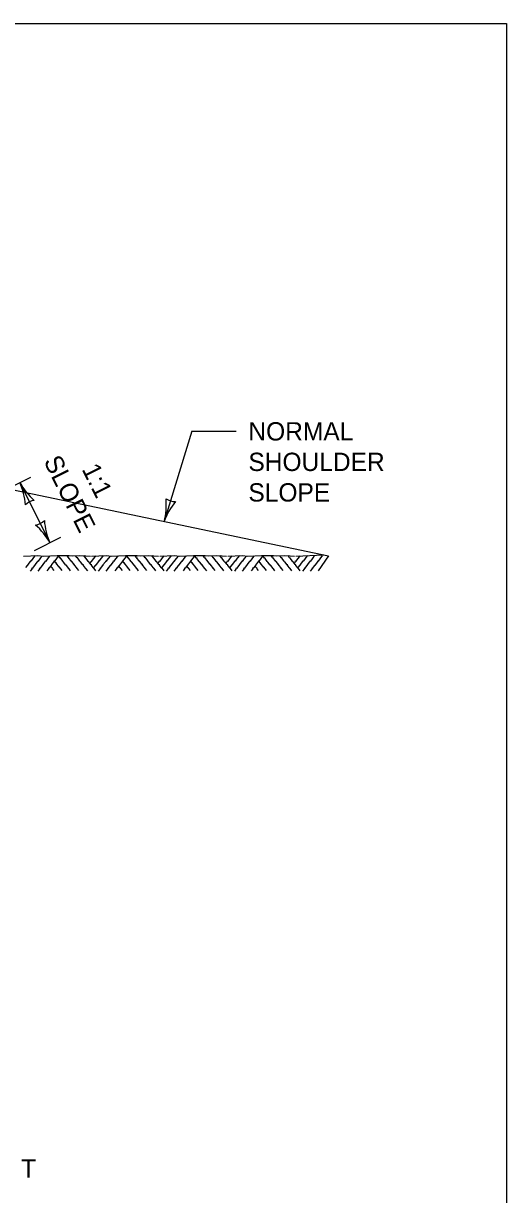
# Model space of a CAD drawing. Extents: x 49991.4 to 50022.1, y 49985 to 50011.4.
# Drawn here: x 50015.17 to 50016.75, y 49995.163 to 49998.999 of the extents above; entities that cross this region are included whole.
import ezdxf

# ---------------------------------------------------------------- set-up
doc = ezdxf.new("R2010")
doc.units = 0
for name, color, linetype in [('Level 1', 7, 'Continuous'), ('Level 2', 7, 'Continuous'), ('Level 3', 7, 'Continuous'), ('Level 4', 7, 'Continuous')]:
    doc.layers.add(name, color=color, linetype=linetype)

msp = doc.modelspace()

# ---------------------------------------------------------------- linework, layer by layer
at = {"layer": 'Level 1'}
msp.add_line((50016.1675, 49997.2547), (50016.1336, 49997.2064), dxfattribs=at)
msp.add_lwpolyline([(49999.3835, 49998.9992), (50016.7501, 49998.9992), (50016.7501, 49987.7988), (49999.3835, 49987.7988)], close=True, dxfattribs=at)
for points in [[(50015.1698, 49997.2545), (50015.217, 49997.2564), (50015.2349, 49997.2545), (50015.2805, 49997.256), (50015.3189, 49997.2562), (50015.3296, 49997.2548), (50015.3546, 49997.2564), (50015.3738, 49997.2554), (50015.3885, 49997.2545)], [(50015.2078, 49997.2562), (50015.2018, 49997.249), (50015.2025, 49997.2474), (50015.201, 49997.2474), (50015.1936, 49997.238), (50015.1916, 49997.238), (50015.192, 49997.2364), (50015.1842, 49997.2268), (50015.1842, 49997.2248), (50015.1826, 49997.2244), (50015.1764, 49997.2164)], [(50015.2302, 49997.2544), (50015.2247, 49997.2478), (50015.2256, 49997.2462), (50015.2241, 49997.2462), (50015.2166, 49997.2368), (50015.2146, 49997.2368), (50015.2148, 49997.235), (50015.2072, 49997.2254), (50015.2072, 49997.2234), (50015.2056, 49997.223), (50015.1982, 49997.2134), (50015.1965, 49997.2134), (50015.1968, 49997.2114), (50015.1916, 49997.2052)], [(50015.2559, 49997.2552), (50015.2499, 49997.2479), (50015.2506, 49997.2464), (50015.2492, 49997.2464), (50015.2418, 49997.237), (50015.2397, 49997.237), (50015.24, 49997.2352), (50015.2325, 49997.2256), (50015.2325, 49997.2239), (50015.2307, 49997.2232), (50015.2235, 49997.2138), (50015.2216, 49997.2136), (50015.222, 49997.2119), (50015.2168, 49997.2053)], [(50015.2853, 49997.256), (50015.2793, 49997.2488), (50015.28, 49997.2473), (50015.2787, 49997.2473), (50015.2712, 49997.238), (50015.2694, 49997.238), (50015.2696, 49997.236), (50015.2619, 49997.2264), (50015.2619, 49997.2248), (50015.2602, 49997.224), (50015.2529, 49997.2148), (50015.2512, 49997.2144), (50015.2514, 49997.2128), (50015.2463, 49997.2064)], [(50015.3237, 49997.2064), (50015.3189, 49997.2126), (50015.3174, 49997.2124), (50015.3177, 49997.2138), (50015.3102, 49997.223), (50015.3106, 49997.225), (50015.3087, 49997.225), (50015.3012, 49997.2348), (50015.2994, 49997.2352), (50015.2992, 49997.2368), (50015.2918, 49997.2462), (50015.2919, 49997.2479), (50015.2901, 49997.248), (50015.285, 49997.2546)], [(50015.3512, 49997.2068), (50015.3456, 49997.2142), (50015.3438, 49997.2138), (50015.3442, 49997.2154), (50015.3368, 49997.2246), (50015.337, 49997.2264), (50015.3354, 49997.2268), (50015.3278, 49997.2364), (50015.3261, 49997.2366), (50015.3258, 49997.2384), (50015.3182, 49997.2478), (50015.3186, 49997.2496), (50015.3166, 49997.2496), (50015.3116, 49997.2562)], [(50015.3798, 49997.2064), (50015.3742, 49997.2134), (50015.3728, 49997.2132), (50015.373, 49997.2144), (50015.3656, 49997.2239), (50015.366, 49997.2258), (50015.364, 49997.226), (50015.3566, 49997.2354), (50015.3548, 49997.2359), (50015.3546, 49997.2378), (50015.3471, 49997.247), (50015.3472, 49997.2488), (50015.3456, 49997.2488), (50015.3405, 49997.2554)], [(50015.3903, 49997.2268), (50015.3832, 49997.2358), (50015.3816, 49997.236), (50015.3813, 49997.2378), (50015.3736, 49997.2472), (50015.3741, 49997.249), (50015.3722, 49997.249), (50015.3669, 49997.2558)], [(50015.4059, 49997.255), (50015.3999, 49997.2479), (50015.4006, 49997.2464), (50015.3992, 49997.2464), (50015.3916, 49997.237), (50015.3908, 49997.237)], [(50015.3926, 49997.2545), (50015.4398, 49997.2564), (50015.4576, 49997.2545), (50015.5032, 49997.256), (50015.5416, 49997.2562), (50015.5523, 49997.2548), (50015.5772, 49997.2564), (50015.5964, 49997.2554), (50015.6112, 49997.2545)], [(50015.4305, 49997.2562), (50015.4245, 49997.249), (50015.4252, 49997.2474), (50015.4238, 49997.2474), (50015.4164, 49997.238), (50015.4143, 49997.238), (50015.4148, 49997.2364), (50015.4071, 49997.2268), (50015.4071, 49997.2248), (50015.4053, 49997.2244), (50015.3993, 49997.2164)], [(50015.453, 49997.2544), (50015.4476, 49997.2478), (50015.448, 49997.2462), (50015.4467, 49997.2462), (50015.4392, 49997.2368), (50015.4374, 49997.2368), (50015.4376, 49997.235), (50015.4299, 49997.2254), (50015.4299, 49997.2234), (50015.4284, 49997.223), (50015.421, 49997.2134), (50015.4192, 49997.2134), (50015.4196, 49997.2114), (50015.4143, 49997.2052)], [(50015.4786, 49997.2552), (50015.4726, 49997.2479), (50015.4734, 49997.2464), (50015.4719, 49997.2464), (50015.4644, 49997.237), (50015.4626, 49997.237), (50015.4629, 49997.2352), (50015.4551, 49997.2256), (50015.4551, 49997.2239), (50015.4536, 49997.2232), (50015.4462, 49997.2138), (50015.4443, 49997.2136), (50015.4448, 49997.2119), (50015.4395, 49997.2053)], [(50015.508, 49997.256), (50015.502, 49997.2488), (50015.5028, 49997.2473), (50015.5016, 49997.2473), (50015.4941, 49997.238), (50015.4922, 49997.238), (50015.4923, 49997.236), (50015.4846, 49997.2264), (50015.4846, 49997.2248), (50015.483, 49997.224), (50015.4756, 49997.2148), (50015.474, 49997.2144), (50015.4743, 49997.2128), (50015.469, 49997.2064)], [(50015.5466, 49997.2064), (50015.5418, 49997.2126), (50015.5402, 49997.2124), (50015.5406, 49997.2138), (50015.5331, 49997.223), (50015.5334, 49997.225), (50015.5316, 49997.225), (50015.5241, 49997.2348), (50015.5223, 49997.2352), (50015.522, 49997.2368), (50015.5145, 49997.2462), (50015.5148, 49997.2479), (50015.513, 49997.248), (50015.5079, 49997.2546)], [(50015.5738, 49997.2068), (50015.5682, 49997.2142), (50015.5666, 49997.2138), (50015.567, 49997.2154), (50015.5595, 49997.2246), (50015.5598, 49997.2264), (50015.5582, 49997.2268), (50015.5505, 49997.2364), (50015.5487, 49997.2366), (50015.5486, 49997.2384), (50015.5409, 49997.2478), (50015.5412, 49997.2496), (50015.5394, 49997.2496), (50015.5343, 49997.2562)], [(50015.6026, 49997.2064), (50015.597, 49997.2134), (50015.5955, 49997.2132), (50015.5958, 49997.2144), (50015.5883, 49997.2239), (50015.5888, 49997.2258), (50015.5868, 49997.226), (50015.5793, 49997.2354), (50015.5775, 49997.2359), (50015.5772, 49997.2378), (50015.5697, 49997.247), (50015.5702, 49997.2488), (50015.5682, 49997.2488), (50015.5632, 49997.2554)], [(50015.613, 49997.2268), (50015.606, 49997.2358), (50015.6042, 49997.236), (50015.604, 49997.2378), (50015.5964, 49997.2472), (50015.5967, 49997.249), (50015.5949, 49997.249), (50015.5895, 49997.2558)], [(50015.6286, 49997.255), (50015.6226, 49997.2479), (50015.6234, 49997.2464), (50015.6219, 49997.2464), (50015.6144, 49997.237), (50015.6135, 49997.237)], [(50015.6156, 49997.2545), (50015.6626, 49997.2564), (50015.6804, 49997.2545), (50015.726, 49997.256), (50015.7644, 49997.2562), (50015.775, 49997.2548), (50015.8001, 49997.2564), (50015.8193, 49997.2554), (50015.834, 49997.2545)], [(50015.6532, 49997.2562), (50015.6472, 49997.249), (50015.648, 49997.2474), (50015.6465, 49997.2474), (50015.6392, 49997.238), (50015.637, 49997.238), (50015.6375, 49997.2364), (50015.6297, 49997.2268), (50015.6297, 49997.2248), (50015.628, 49997.2244), (50015.622, 49997.2164)], [(50015.6758, 49997.2544), (50015.6702, 49997.2478), (50015.6708, 49997.2462), (50015.6696, 49997.2462), (50015.6621, 49997.2368), (50015.6602, 49997.2368), (50015.6603, 49997.235), (50015.6526, 49997.2254), (50015.6526, 49997.2234), (50015.6512, 49997.223), (50015.6438, 49997.2134), (50015.642, 49997.2134), (50015.6423, 49997.2114), (50015.637, 49997.2052)], [(50015.7014, 49997.2552), (50015.6954, 49997.2479), (50015.6962, 49997.2464), (50015.6946, 49997.2464), (50015.6873, 49997.237), (50015.6852, 49997.237), (50015.6856, 49997.2352), (50015.678, 49997.2256), (50015.678, 49997.2239), (50015.6762, 49997.2232), (50015.669, 49997.2138), (50015.667, 49997.2136), (50015.6675, 49997.2119), (50015.6622, 49997.2053)], [(50015.7308, 49997.256), (50015.7248, 49997.2488), (50015.7256, 49997.2473), (50015.7242, 49997.2473), (50015.7167, 49997.238), (50015.7149, 49997.238), (50015.715, 49997.236), (50015.7074, 49997.2264), (50015.7074, 49997.2248), (50015.7058, 49997.224), (50015.6984, 49997.2148), (50015.6968, 49997.2144), (50015.697, 49997.2128), (50015.6918, 49997.2064)], [(50015.7692, 49997.2064), (50015.7644, 49997.2126), (50015.7629, 49997.2124), (50015.7632, 49997.2138), (50015.7556, 49997.223), (50015.7562, 49997.225), (50015.7542, 49997.225), (50015.7467, 49997.2348), (50015.745, 49997.2352), (50015.7448, 49997.2368), (50015.7372, 49997.2462), (50015.7376, 49997.2479), (50015.7358, 49997.248), (50015.7306, 49997.2546)], [(50015.7966, 49997.2068), (50015.7911, 49997.2142), (50015.7893, 49997.2138), (50015.7898, 49997.2154), (50015.7822, 49997.2246), (50015.7826, 49997.2264), (50015.7809, 49997.2268), (50015.7732, 49997.2364), (50015.7716, 49997.2366), (50015.7713, 49997.2384), (50015.7638, 49997.2478), (50015.7641, 49997.2496), (50015.7622, 49997.2496), (50015.757, 49997.2562)], [(50015.8253, 49997.2064), (50015.8198, 49997.2134), (50015.8182, 49997.2132), (50015.8186, 49997.2144), (50015.811, 49997.2239), (50015.8115, 49997.2258), (50015.8096, 49997.226), (50015.802, 49997.2354), (50015.8004, 49997.2359), (50015.8001, 49997.2378), (50015.7926, 49997.247), (50015.7929, 49997.2488), (50015.7911, 49997.2488), (50015.786, 49997.2554)], [(50015.8358, 49997.2268), (50015.8288, 49997.2358), (50015.8271, 49997.236), (50015.8268, 49997.2378), (50015.8192, 49997.2472), (50015.8196, 49997.249), (50015.8176, 49997.249), (50015.8122, 49997.2558)], [(50015.8514, 49997.255), (50015.8454, 49997.2479), (50015.8462, 49997.2464), (50015.8446, 49997.2464), (50015.8372, 49997.237), (50015.8362, 49997.237)], [(50015.838, 49997.2545), (50015.8853, 49997.2564), (50015.9032, 49997.2545), (50015.9488, 49997.256), (50015.9872, 49997.2562), (50015.9978, 49997.2548), (50016.0227, 49997.2564), (50016.042, 49997.2554), (50016.0568, 49997.2545)], [(50015.876, 49997.2562), (50015.87, 49997.249), (50015.8708, 49997.2474), (50015.8692, 49997.2474), (50015.8619, 49997.238), (50015.8598, 49997.238), (50015.8602, 49997.2364), (50015.8526, 49997.2268), (50015.8526, 49997.2248), (50015.8508, 49997.2244), (50015.8448, 49997.2164)], [(50015.8985, 49997.2544), (50015.8931, 49997.2478), (50015.8937, 49997.2462), (50015.8922, 49997.2462), (50015.8847, 49997.2368), (50015.8829, 49997.2368), (50015.883, 49997.235), (50015.8754, 49997.2254), (50015.8754, 49997.2234), (50015.8739, 49997.223), (50015.8664, 49997.2134), (50015.8648, 49997.2134), (50015.865, 49997.2114), (50015.8598, 49997.2052)], [(50015.9242, 49997.2552), (50015.9182, 49997.2479), (50015.9189, 49997.2464), (50015.9174, 49997.2464), (50015.91, 49997.237), (50015.9081, 49997.237), (50015.9084, 49997.2352), (50015.9008, 49997.2256), (50015.9008, 49997.2239), (50015.8991, 49997.2232), (50015.8918, 49997.2138), (50015.8898, 49997.2136), (50015.8902, 49997.2119), (50015.885, 49997.2053)], [(50015.9536, 49997.256), (50015.9477, 49997.2488), (50015.9483, 49997.2473), (50015.9471, 49997.2473), (50015.9396, 49997.238), (50015.9376, 49997.238), (50015.9378, 49997.236), (50015.9302, 49997.2264), (50015.9302, 49997.2248), (50015.9285, 49997.224), (50015.9212, 49997.2148), (50015.9195, 49997.2144), (50015.9198, 49997.2128), (50015.9146, 49997.2064)], [(50015.9921, 49997.2064), (50015.9872, 49997.2126), (50015.9856, 49997.2124), (50015.9861, 49997.2138), (50015.9786, 49997.223), (50015.9789, 49997.225), (50015.9771, 49997.225), (50015.9696, 49997.2348), (50015.9676, 49997.2352), (50015.9675, 49997.2368), (50015.96, 49997.2462), (50015.9602, 49997.2479), (50015.9585, 49997.248), (50015.9534, 49997.2546)], [(50016.0194, 49997.2068), (50016.0137, 49997.2142), (50016.012, 49997.2138), (50016.0125, 49997.2154), (50016.005, 49997.2246), (50016.0053, 49997.2264), (50016.0036, 49997.2268), (50015.996, 49997.2364), (50015.9942, 49997.2366), (50015.994, 49997.2384), (50015.9864, 49997.2478), (50015.9867, 49997.2496), (50015.9849, 49997.2496), (50015.9798, 49997.2562)], [(50016.048, 49997.2064), (50016.0425, 49997.2134), (50016.041, 49997.2132), (50016.0413, 49997.2144), (50016.0338, 49997.2239), (50016.0342, 49997.2258), (50016.0326, 49997.226), (50016.0248, 49997.2354), (50016.0232, 49997.2359), (50016.0227, 49997.2378), (50016.0152, 49997.247), (50016.0156, 49997.2488), (50016.0137, 49997.2488), (50016.0088, 49997.2554)], [(50016.0586, 49997.2268), (50016.0515, 49997.2358), (50016.0497, 49997.236), (50016.0496, 49997.2378), (50016.0419, 49997.2472), (50016.0422, 49997.249), (50016.0404, 49997.249), (50016.0352, 49997.2558)], [(50016.0742, 49997.255), (50016.0682, 49997.2479), (50016.0689, 49997.2464), (50016.0674, 49997.2464), (50016.0599, 49997.237), (50016.059, 49997.237)], [(50016.0608, 49997.2545), (50016.1512, 49997.2581)], [(50016.0988, 49997.2562), (50016.0928, 49997.249), (50016.0935, 49997.2474), (50016.092, 49997.2474), (50016.0846, 49997.238), (50016.0826, 49997.238), (50016.083, 49997.2364), (50016.0752, 49997.2268), (50016.0752, 49997.2248), (50016.0736, 49997.2244), (50016.0676, 49997.2164)], [(50016.1212, 49997.2544), (50016.1157, 49997.2478), (50016.1166, 49997.2462), (50016.1151, 49997.2462), (50016.1076, 49997.2368), (50016.1056, 49997.2368), (50016.1058, 49997.235), (50016.0982, 49997.2254), (50016.0982, 49997.2234), (50016.0966, 49997.223), (50016.0893, 49997.2134), (50016.0875, 49997.2134), (50016.0878, 49997.2114), (50016.0826, 49997.2052)], [(50016.1469, 49997.2552), (50016.1409, 49997.2479), (50016.1416, 49997.2464), (50016.1402, 49997.2464), (50016.1326, 49997.237), (50016.1307, 49997.237), (50016.1312, 49997.2352), (50016.1235, 49997.2256), (50016.1235, 49997.2239), (50016.1217, 49997.2232), (50016.1145, 49997.2138), (50016.1126, 49997.2136), (50016.113, 49997.2119), (50016.1078, 49997.2053)], [(50015.2706, 49997.2066), (50015.2652, 49997.2134), (50015.2655, 49997.215), (50015.2636, 49997.2154), (50015.2586, 49997.2218)], [(50015.2962, 49997.2072), (50015.2876, 49997.218), (50015.2859, 49997.2185), (50015.2858, 49997.2203), (50015.2782, 49997.2294), (50015.2784, 49997.2314), (50015.2766, 49997.2314), (50015.2716, 49997.2378)], [(50015.3906, 49997.237), (50015.3896, 49997.237), (50015.3897, 49997.2352), (50015.387, 49997.2316)], [(50015.4068, 49997.2065), (50015.4014, 49997.2136), (50015.3998, 49997.2132), (50015.4, 49997.2148), (50015.3926, 49997.224), (50015.393, 49997.226), (50015.3912, 49997.2262), (50015.3908, 49997.2268)], [(50015.4932, 49997.2066), (50015.4881, 49997.2134), (50015.4882, 49997.215), (50015.4863, 49997.2154), (50015.4812, 49997.2218)], [(50015.519, 49997.2072), (50015.5103, 49997.218), (50015.5086, 49997.2185), (50015.5085, 49997.2203), (50015.501, 49997.2294), (50015.5012, 49997.2314), (50015.4992, 49997.2314), (50015.4944, 49997.2378)], [(50015.6132, 49997.237), (50015.6123, 49997.237), (50015.6126, 49997.2352), (50015.6098, 49997.2316)], [(50015.6296, 49997.2065), (50015.6242, 49997.2136), (50015.6225, 49997.2132), (50015.6228, 49997.2148), (50015.6153, 49997.224), (50015.6158, 49997.226), (50015.6141, 49997.2262), (50015.6135, 49997.2268)], [(50015.7162, 49997.2066), (50015.7107, 49997.2134), (50015.711, 49997.215), (50015.709, 49997.2154), (50015.7041, 49997.2218)], [(50015.7418, 49997.2072), (50015.733, 49997.218), (50015.7314, 49997.2185), (50015.7312, 49997.2203), (50015.7238, 49997.2294), (50015.7239, 49997.2314), (50015.7221, 49997.2314), (50015.717, 49997.2378)], [(50015.8361, 49997.237), (50015.835, 49997.237), (50015.8355, 49997.2352), (50015.8325, 49997.2316)], [(50015.8523, 49997.2065), (50015.8469, 49997.2136), (50015.8454, 49997.2132), (50015.8456, 49997.2148), (50015.838, 49997.224), (50015.8385, 49997.226), (50015.8367, 49997.2262), (50015.8362, 49997.2268)], [(50015.9387, 49997.2066), (50015.9336, 49997.2134), (50015.9338, 49997.215), (50015.9318, 49997.2154), (50015.9267, 49997.2218)], [(50015.9645, 49997.2072), (50015.9558, 49997.218), (50015.9542, 49997.2185), (50015.954, 49997.2203), (50015.9465, 49997.2294), (50015.9466, 49997.2314), (50015.9447, 49997.2314), (50015.9399, 49997.2378)], [(50016.0587, 49997.237), (50016.0578, 49997.237), (50016.0582, 49997.2352), (50016.0552, 49997.2316)], [(50016.075, 49997.2065), (50016.0696, 49997.2136), (50016.0682, 49997.2132), (50016.0683, 49997.2148), (50016.0608, 49997.224), (50016.0612, 49997.226), (50016.0596, 49997.2262), (50016.059, 49997.2268)]]:
    msp.add_lwpolyline(points, dxfattribs=at)
at = {"layer": 'Level 3'}
for p, q in [((50015.7208, 49997.663), (50015.6302, 49997.3677)), ((50015.7208, 49997.663), (50015.8656, 49997.663)), ((50015.107, 49997.4697), (50015.1939, 49997.513)), ((50015.158, 49997.4951), (50015.2562, 49997.2979)), ((50015.2054, 49997.2726), (50015.2921, 49997.3158))]:
    msp.add_line(p, q, dxfattribs=at)
for centre, radius, start, end in [((50014.9632, 49997.408), 0.2134, 3.9205, 24.104), ((50015.3531, 49997.6046), 0.2237, 209.2918, 228.5417), ((50015.4133, 49997.4227), 0.2237, 345.7744, 5.0243), ((50015.6663, 49997.4854), 0.0526, 235.0859, 270.8083), ((50015.2129, 49997.3849), 0.0526, 98.6033, 134.3257), ((50015.8315, 49997.2968), 0.2134, 140.4031, 160.5866), ((50015.2013, 49997.4081), 0.0526, 278.6033, 314.3257), ((50015.451, 49997.3851), 0.2134, 183.9205, 204.104), ((50015.0611, 49997.1885), 0.2237, 29.2918, 48.5417)]:
    msp.add_arc(centre, radius, start, end, dxfattribs=at)
at = {"layer": 'Level 4'}
msp.add_line((50014.8017, 49997.542), (50016.1675, 49997.2547), dxfattribs=at)

# ---------------------------------------------------------------- texts
at = {"layer": 'Level 2'}
for s, p in [('NORMAL', (50015.9056, 49997.633)), ('SHOULDER', (50015.9056, 49997.533)), ('SLOPE', (50015.9056, 49997.433)), ('T', (50015.1621, 49995.2186))]:
    msp.add_text(s, height=0.06, dxfattribs=at).set_placement(p)
for s, p in [('SLOPE', (50015.2347, 49997.5654)), ('1:1', (50015.3595, 49997.5391))]:
    msp.add_text(s, height=0.06, rotation=296.4886, dxfattribs=at).set_placement(p)

doc.saveas('drawing.dxf')
